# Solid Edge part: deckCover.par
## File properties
Author: morva
Template: iso metric part.par
Last saved by: morva
Revision: 33
Application: Solid Edge
Density: 1385.000 kg/m^3
Accuracy: 0.990
Username: morva
Material: PVC
Face Style: Tan
Fill Style: ANSI34(Plastic)
Virtual Style: ANSI34(Plastic)
Grouping: Non-metals\Plastics
LibraryName: Materials
Coef. of Thermal Exp: 9e-05
Thermal Conductivity: 1.5
Specific Heat: 0.0
Modulus of Elasticity: 2757903000.0
Poisson's Ratio: 0.4
Yield Stress: 6894757.0
Ultimate Stress: 0.0
Elongation: 0.0
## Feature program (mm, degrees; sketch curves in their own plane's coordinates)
sketch for "unnamed Protrusion 1" plane through (0, 0, 0) normal (0, 0, 1) x-axis (1, 0, 0)
  line (-413.2539, 25) -> (-293.9843, 125)
  line (-293.9843, 125) -> (293.9843, 125)
  line (293.9843, 125) -> (369.6761, 72)
  line (369.6761, 72) -> (364.6314, 56)
  line (364.6314, 56) -> (269.6761, 22.5)
  line (269.6761, 22.5) -> (269.6761, -22.5)
  line (269.6761, -22.5) -> (364.6314, -56)
  line (369.6761, -72) -> (364.6314, -56)
  line (293.9843, -125) -> (369.6761, -72)
  line (-293.9843, -125) -> (293.9843, -125)
  line (-413.2539, -25) -> (-293.9843, -125)
  line (-470.3239, -25) -> (-413.2539, -25)
  line (-470.3239, 25) -> (-470.3239, -25)
  line (-470.3239, 25) -> (-413.2539, 25)
  dimension (linear) = 470.3239
  dimension (linear) = 413.2539
  dimension (linear) = 293.9843
  dimension (linear) = 269.6761
  dimension (linear) = 293.9843
  dimension (linear) = 364.6314
  dimension (linear) = 369.6761
extrude "unnamed Protrusion 1" add finite 5 along -normal
sketch for "Hole_11" plane through (-50.3239, 0, 0) normal (0, 0, 1) x-axis (1, 0, 0)
  hole centre (309.2682, 116) bore radius 4.2
  dimension (linear) = 309.2682
hole "Hole_11" diameter 8.4 through  CounterSinkAngle = 90 deg; Head_Clearance = 0.4 mm
sketch for "unnamed Hole 1" plane through (-50.3239, 0, 0) normal (0, 0, 1) x-axis (1, 0, 0)
  hole centre (-222.8405, 116) bore radius 4.2
hole "unnamed Hole 1" through
sketch for "unnamed Hole 2" plane through (-50.3239, 0, 0) normal (0, 0, 1) x-axis (1, 0, 0)
  hole centre (-405, 16) bore radius 4.2
hole "unnamed Hole 2" through
sketch for "unnamed Hole 3" plane through (-50.3239, 0, 0) normal (0, 0, 1) x-axis (1, 0, 0)
  hole centre (407.9552, 63) bore radius 4.2
hole "unnamed Hole 3" through
pattern "unnamed Pattern 1" of "Hole_11", "unnamed Hole 1", "unnamed Hole 2", "unnamed Hole 3"
mirror "unnamed Mirror 1" of "unnamed Pattern 1"
pattern "unnamed Pattern 2"
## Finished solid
Body 1: solid body, 40 faces, 74 edges, 28 vertices.
  Faces by surface: cylinder 16, plane 16, cone 8
  Edges by curve: line 42, circle 32
Bounding box of the edges (mm): 840.000 x 250.000 x 5.000, from (-470.3239, -125, -5) to (369.6761, 125, 0).
Cylindrical faces by radius (mm): R4.2 x8, R8 x8
Conical faces (half-angle, radius in mm at the cone's reference point): 45 deg R8 x8
Planar faces by outward normal: +x 1, +y 2, +z 1, -x 1, -y 2, -z 1, oblique 8
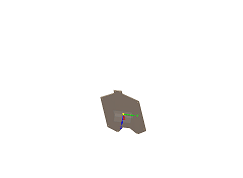
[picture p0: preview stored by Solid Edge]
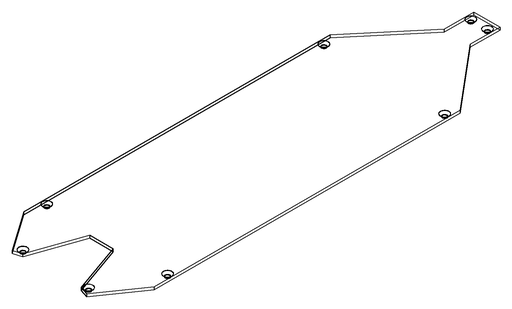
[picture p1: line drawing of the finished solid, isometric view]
